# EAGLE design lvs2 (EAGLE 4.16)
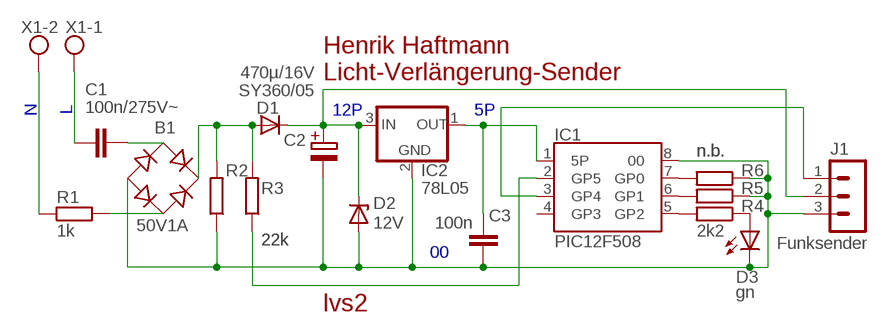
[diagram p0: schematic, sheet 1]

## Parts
B1  50V1A  RB1A  [RB1A]
C1  100n/275V~  C15  [C150-084X183]
C2  470µ/16V  E02-10  [E02-10]
C3  100n  C02  [C2]
D1  SY360/05  D01  [R01]
D2  12V  DZ01  [R01]
D3  gn  LED3MM  [LED3MM]
IC1  PIC12F508  PIC12FP  [DIL08]
IC2  78L05  78XX92/  [TO92/]
J1  Funksender  MA03-1  [MA03-1]
R1  1k  R01  [R01]
R2  22k  R01  [R01]
R3  22k  R01  [R01]
R4  2k2  R01  [R01]
R5  n.b.  R1206  [1206]
R6  n.b.  R1206  [1206]
X1  W237-02P  [W237-132]

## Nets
00: B1.- C2.- C3.2 D2.1(A) D3.K IC1.8 IC2.2(GND) J1.3 R2.1 R5.1 R6.1
5P: C3.1 IC1.1(5P) IC2.1(OUT)
12P: C2.+ D1.2(K) D2.2(K) IC2.3(IN) J1.2
!ZC: IC1.2(GP5) R3.1
L: C1.1 X1.1
N: R1.1 X1.2
N$1: B1.AC2 C1.2
N$2: IC1.3(GP4) J1.1
N$3: B1.+ D1.1(A) R2.2 R3.2
N$4: B1.AC1 R1.2
N$5: IC1.5(GP2) R4.2
N$6: D3.A R4.1
N$7: IC1.6(GP1) R5.2
N$8: IC1.7(GP0) R6.2
Unconnected: IC1.4(GP3)

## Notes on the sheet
- Henrik Haftmann
- Licht-Verlängerung-Sender

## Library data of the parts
B1 = rectifier:RB1A: RECTIFIER 1 A
C1 C3 = fu:C: Kondensator
C2 = fu:E: Elektrolytkondensator, gepolt
D1 = fu:D: Diode
D2 = fu:DZ: Z-Diode
D3 = fu:LED: Leuchtdiode
IC1 = fu:PIC12F*: 8-Bit-Mikrocontroller mit 8 Beinchen TypFlashRAMEEPROMADC 12F508
IC2 = fu:78XX: Spannungsregler positiv (78xx) oder negativ (79xx)
J1 = con-lstb:MA03-1: PIN HEADER
R1-R6 = fu:R: Widerstand
X1 = con-wago-508:W237-02P: WAGO SREW CLAMP

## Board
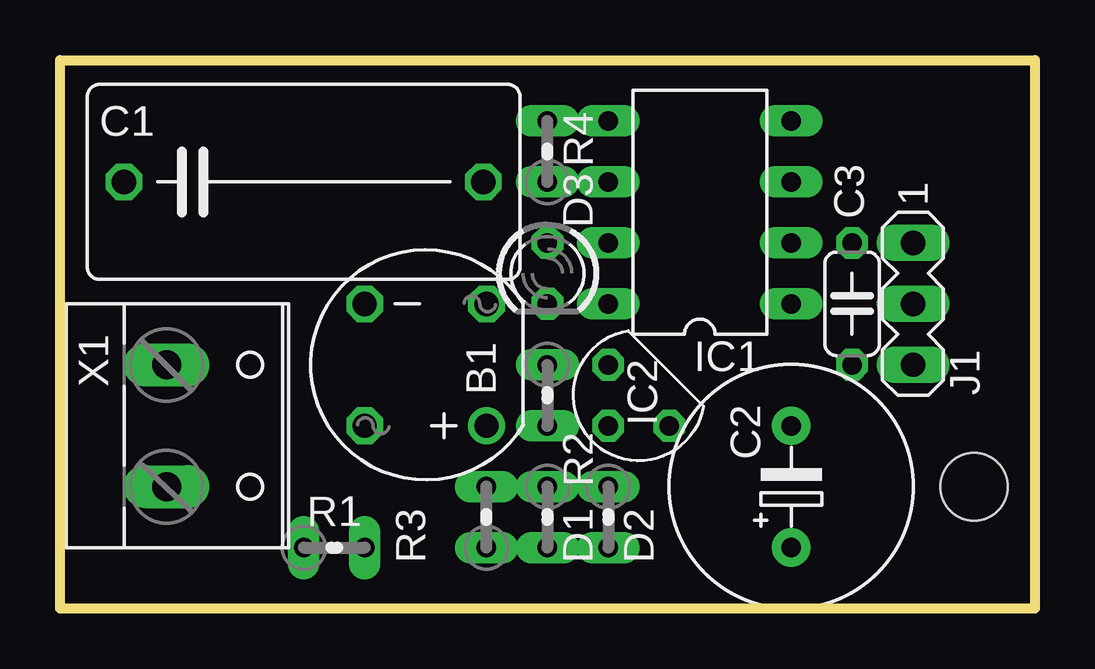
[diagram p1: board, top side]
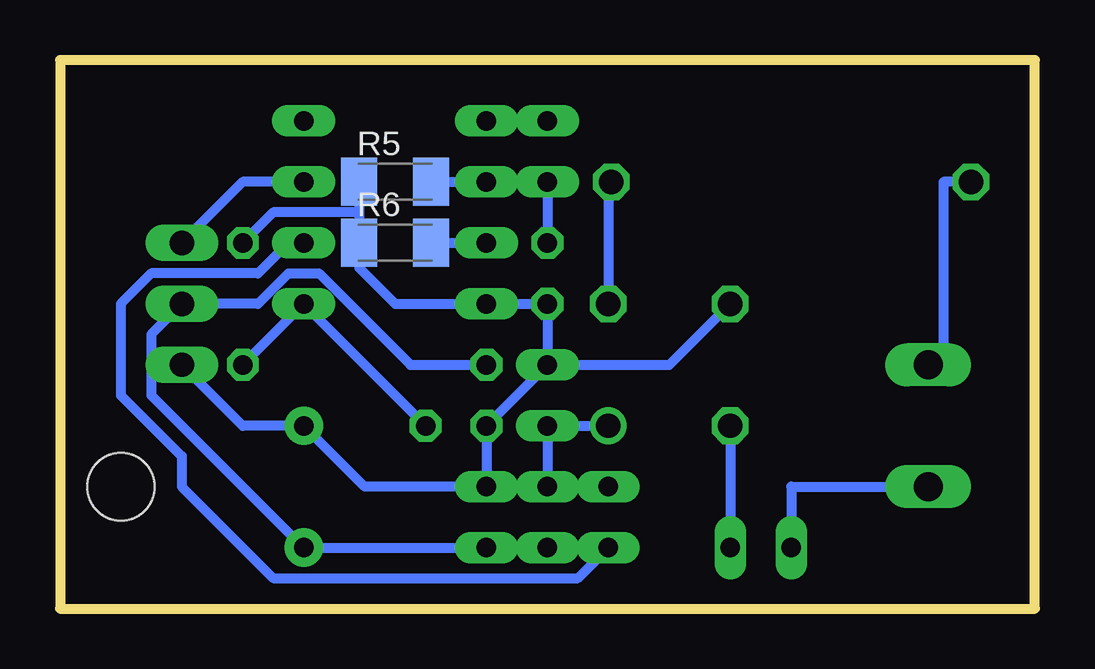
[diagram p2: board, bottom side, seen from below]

Size 40.64 x 22.86 mm. Coordinates in mm from the lower left corner, seen from the top.
Outline: 0,22.86 40.64,22.86 40.64,0 0,0 0,22.86
Copper layers (1*16): Top 0.035mm / dielectric 1.5mm / Bottom 0.035mm
Design rules "default": minimum track width 10mil, minimum drill 0.6mm, track to track 8mil, track to pad 8mil, pad to pad 8mil, via to via 8mil, smd to smd 0mil, copper to edge 0.5mm, drill to drill 8mil, minimum pad ring 10mil, minimum via ring 8mil, stop-mask expansion 4mil, vias tented up to drill 0mil, thermal gap 10mil
Holes 2.8 mm at 38.1,5.08

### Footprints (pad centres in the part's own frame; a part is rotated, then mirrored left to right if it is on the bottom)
RB1A = drill 1.016 round: + -2.54,2.54 | drill 1.016 octagon: - 2.54,-2.54; AC1 2.54,2.54; AC2 -2.54,-2.54
C150-084X183 = drill 1.016 octagon: 1 -7.493,0; 2 7.493,0
E02-10 = drill 0.813 pad 1.6 round: + -2.54,0; - 2.54,0
C2 = drill 0.813 octagon: 1 -2.54,0; 2 2.54,0
R01 = drill 0.813 long: 1 -1.27,0; 2 1.27,0
LED3MM = drill 0.813 octagon: A -1.27,0; K 1.27,0
DIL08 = drill 0.813 long: 1 -3.81,-3.81; 2 -1.27,-3.81; 3 1.27,-3.81; 4 3.81,-3.81; 5 3.81,3.81; 6 1.27,3.81; 7 -1.27,3.81; 8 -3.81,3.81
TO92/ = drill 0.813 octagon: 1 -2.54,0; 2 0,0; 3 0,-2.54
MA03-1 = drill 1.016 long: 1 -2.54,0; 2 0,0; 3 2.54,0
1206 = smd 1.5 x 2: 1 -1.5,0; 2 1.5,0
W237-132 = drill 1.194 long: 1 -2.54,-0.635; 2 2.54,-0.635

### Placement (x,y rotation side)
B1  15.24,10.16 180 top
C1  10.16,17.78 0 top
C2  30.48,5.08 90 top
C3  33.02,12.7 90 top
D1  20.32,3.81 270 top
D2  22.86,3.81 270 top
D3  20.32,13.97 270 top
IC1  26.67,16.51 90 top
IC2  22.86,7.62 180 top
J1  35.56,12.7 270 top
R1  11.43,2.54 0 top
R2  20.32,8.89 270 top
R3  17.78,3.81 90 top
R4  20.32,19.05 90 top
R5  26.67,17.78 0 bottom
R6  26.67,15.24 0 bottom
X1  5.08,7.62 270 top

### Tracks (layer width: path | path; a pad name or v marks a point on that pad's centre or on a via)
00
  Bottom 0.406: R2.1 15.24,10.16 B1.- | R2.1 IC2.2 D2.1 27.94,5.08 C2.- 33.02,7.62 J1.3 | C3.2 31.75,16.51 28.17,16.51 | R2.1 D3.K IC1.8 26.67,12.7 28.17,14.2 R6.1 28.17,16.51 | R5.1 28.17,16.51
5P
  Bottom 0.406: IC2.1 IC1.1 C3.1
12P
  Bottom 0.406: D1.2 D2.2 C2.+ 36.83,8.89 36.83,11.43 J1.2 32.38,12.7 31.11,13.97 29.84,13.97 26.04,10.16 IC2.3
!ZC
  Bottom 0.406: R3.1 19.05,1.27 31.75,1.27 35.56,5.08 35.56,6.35 38.1,8.89 38.1,12.7 36.83,13.97 32.38,13.97 31.11,15.24 IC1.2
L
  Bottom 0.406: X1.1 3.81,10.16 3.81,17.78 C1.1
N
  Bottom 0.406: X1.2 10.16,5.08 R1.1
N$1
  Bottom 0.406: B1.AC2 17.78,17.78 C1.2
N$2
  Bottom 0.406: IC1.3 33.02,17.78 J1.1
N$3
  Bottom 0.406: B1.+ R2.2 D1.1 R3.2
N$4
  Bottom 0.406: B1.AC1 R1.2
N$5
  Bottom 0.406: IC1.5 R4.2
N$6
  Bottom 0.406: R4.1 D3.A
N$7
  Bottom 0.406: R5.2 IC1.6
N$8
  Bottom 0.406: R6.2 IC1.7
